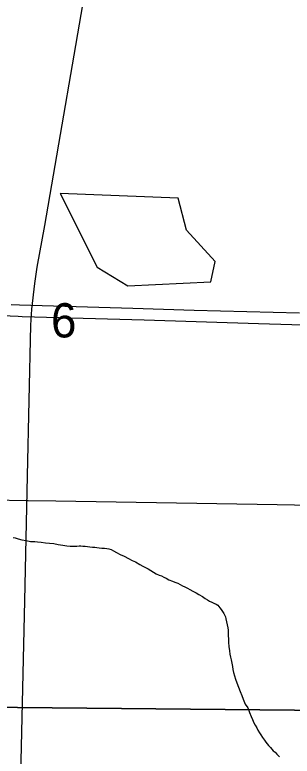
# Model space of a CAD drawing. Extents: x 1587405 to 1714697, y 1028970 to 1155083.
# Drawn here: x 1652910 to 1654699, y 1087021 to 1091803 of the extents above; entities that cross this region are included whole.
import ezdxf

# ---------------------------------------------------------------- set-up
doc = ezdxf.new("R2010")
doc.units = 0
for name, color, linetype in [('GM_X_County_Road', 7, 'Continuous'), ('GM_X_Minor_Lake', 7, 'Continuous'), ('GM_X_Minor_River', 7, 'Continuous'), ('GM_X_Rail_Line', 7, 'Continuous'), ('GM_X_Section', 7, 'Continuous'), ('GM_X_Section_Text', 7, 'Continuous'), ('GM_X_State_Route', 7, 'Continuous')]:
    doc.layers.add(name, color=color, linetype=linetype)

msp = doc.modelspace()

# ---------------------------------------------------------------- linework, layer by layer
at = {"layer": 'GM_X_County_Road'}
for points in [[(1650727, 1088708.1), (1652307.2, 1088683.1), (1652987.6, 1088670.4)], [(1652987.6, 1088670.4), (1652996, 1088670.3), (1653174.8, 1088667), (1654602.3, 1088643.1), (1655947.5, 1088617.9), (1656964.6, 1088594.7), (1657194.3, 1088589.9), (1658162, 1088567), (1658364, 1088563.7)]]:
    msp.add_lwpolyline(points, dxfattribs=at)
at = {"layer": 'GM_X_Minor_Lake'}
for points in [[(1653202, 1090649.3), (1653440.5, 1090174.6), (1653638.3, 1090054), (1654175.1, 1090080.6)], [(1654175.1, 1090080.6), (1654202.5, 1090210.9), (1654017.6, 1090413.8), (1653963.4, 1090619.3), (1653202, 1090649.3)], [(1653202, 1090649.3), (1653440.5, 1090174.6), (1653638.3, 1090054), (1654175.1, 1090080.6), (1654202.5, 1090210.9), (1654017.6, 1090413.8), (1653963.4, 1090619.3), (1653202, 1090649.3)]]:
    msp.add_lwpolyline(points, dxfattribs=at)
at = {"layer": 'GM_X_Minor_River'}
for points in [[(1652898.9, 1088432.1), (1652912.9, 1088427.9), (1652930.9, 1088421.7), (1652955, 1088415.4), (1652983.1, 1088411.1), (1653011.1, 1088404.8), (1653039.3, 1088404.5), (1653057.3, 1088402.3), (1653079.4, 1088400.1), (1653107.5, 1088397.7), (1653133.6, 1088395.5), (1653161.7, 1088393.2), (1653189.8, 1088386.8), (1653219.9, 1088382.5), (1653246, 1088378.2), (1653268.1, 1088376), (1653288.2, 1088375.8), (1653310.3, 1088375.5), (1653324.4, 1088377.4), (1653336.4, 1088377.3), (1653348.5, 1088375.1), (1653364.5, 1088375), (1653378.6, 1088372.8), (1653394.7, 1088370.6), (1653410.7, 1088368.5), (1653426.8, 1088368.3), (1653438.8, 1088366.2), (1653454.9, 1088364), (1653470.9, 1088361.8), (1653489, 1088361.6), (1653503.1, 1088359.5), (1653517.1, 1088357.3), (1653531.1, 1088353.2), (1653547.1, 1088344.9), (1653567.1, 1088334.7), (1653589.1, 1088322.4), (1653615.1, 1088310.1), (1653643.1, 1088295.7), (1653667.1, 1088283.4), (1653689.1, 1088273.1), (1653717.1, 1088256.8), (1653735.1, 1088246.6), (1653753.1, 1088238.3), (1653771.1, 1088228.1), (1653823, 1088197.4), (1653841, 1088189.2), (1653857.1, 1088183), (1653871, 1088174.8), (1653887.1, 1088168.6), (1653903, 1088158.4), (1653927.1, 1088150.1), (1653943.1, 1088143.9), (1653961.1, 1088135.7), (1653977.1, 1088127.5), (1653991.1, 1088119.3), (1654007.1, 1088113.1), (1654023.1, 1088104.9), (1654039.1, 1088096.7), (1654059.1, 1088084.4), (1654079.1, 1088074.2), (1654097.1, 1088064), (1654121, 1088049.6), (1654139, 1088037.4), (1654153, 1088029.2), (1654167, 1088021), (1654181, 1088014.9), (1654195, 1088006.7), (1654209, 1088000.5), (1654219, 1087994.4)], [(1654219, 1087994.4), (1654232.9, 1087978.2), (1654240.8, 1087966), (1654250.7, 1087953.8), (1654258.6, 1087941.7), (1654262.6, 1087931.6), (1654268.5, 1087919.5), (1654272.4, 1087907.4), (1654283.9, 1087849), (1654285.7, 1087832.9), (1654287.6, 1087814.8), (1654287.4, 1087796.7), (1654289.2, 1087776.6), (1654289, 1087754.5), (1654290.7, 1087728.4), (1654294.5, 1087700.2), (1654298.3, 1087678.1), (1654302.1, 1087659.9), (1654305.9, 1087641.8), (1654309.7, 1087619.7), (1654313.6, 1087599.5), (1654317.4, 1087579.4), (1654321.2, 1087559.3), (1654327, 1087539.1), (1654334.9, 1087516.9), (1654342.7, 1087492.7), (1654352.5, 1087466.5), (1654364.2, 1087438.3), (1654374, 1087412), (1654383.8, 1087387.8), (1654395.6, 1087355.6), (1654413.4, 1087331.3), (1654423.2, 1087303), (1654435, 1087276.8), (1654442.8, 1087256.6), (1654452.7, 1087236.4), (1654460.6, 1087220.2), (1654470.5, 1087204.1), (1654478.4, 1087187.9), (1654488.2, 1087171.7), (1654498.1, 1087157.6), (1654508, 1087141.4), (1654519.9, 1087123.2), (1654529.8, 1087111), (1654537.8, 1087100.9), (1654547.7, 1087088.7), (1654559.7, 1087076.6), (1654567.6, 1087066.4), (1654577.5, 1087054.3), (1654589.5, 1087046.1), (1654601.4, 1087033.9), (1654617.3, 1087015.7)]]:
    msp.add_lwpolyline(points, dxfattribs=at)
at = {"layer": 'GM_X_Rail_Line'}
msp.add_lwpolyline([(1652796, 1071361.6), (1652803.3, 1076712.2), (1652808.2, 1079355), (1652854, 1082035.8), (1652901.5, 1084675), (1652938.1, 1086425.3), (1652974.1, 1088023.5), (1652991.4, 1088829.1), (1653013.7, 1089801.4), (1653020.3, 1089903.6), (1653039.4, 1090069.9), (1653054.2, 1090175.8), (1653104.6, 1090443.3), (1653394, 1092132.5)], dxfattribs=at)
at = {"layer": 'GM_X_Section'}
for points in [[(1650760.9, 1092453), (1655871.3, 1092400.1), (1655606.5, 1087308.4), (1650692.2, 1087356.8)], [(1650692.2, 1087356.8), (1655606.5, 1087308.4), (1655510.9, 1081994.5), (1653003.1, 1082045.4), (1650640.4, 1082028.3), (1650688.2, 1087202.8)]]:
    msp.add_lwpolyline(points, close=True, dxfattribs=at)
at = {"layer": 'GM_X_State_Route'}
for points in [[(1652886.7, 1089933.9), (1652941.3, 1089932.4), (1653672, 1089909.9), (1654067.6, 1089898.5), (1654746.8, 1089880.1)], [(1652777.4, 1089864.3), (1652930.7, 1089858.7)], [(1652930.7, 1089858.7), (1652957.6, 1089857.7), (1653744.4, 1089834.3), (1654481.9, 1089812.4), (1655055.6, 1089795.1), (1656153.9, 1089764.5), (1657088.3, 1089736.9), (1657383.2, 1089727.3), (1657760.3, 1089717.8), (1659219.2, 1089675.2), (1660006, 1089651.8), (1660530.5, 1089636.7), (1661126.5, 1089618.1), (1661573.2, 1089604.5), (1661901.7, 1089596), (1662522.3, 1089580.6), (1663129.3, 1089562.6), (1664326.7, 1089527.5)]]:
    msp.add_lwpolyline(points, dxfattribs=at)

# ---------------------------------------------------------------- texts
at = {"layer": 'GM_X_Section_Text'}
msp.add_text('6', height=221, rotation=0, dxfattribs=at).set_placement((1653143.6, 1089721.6))

doc.saveas('drawing.dxf')
